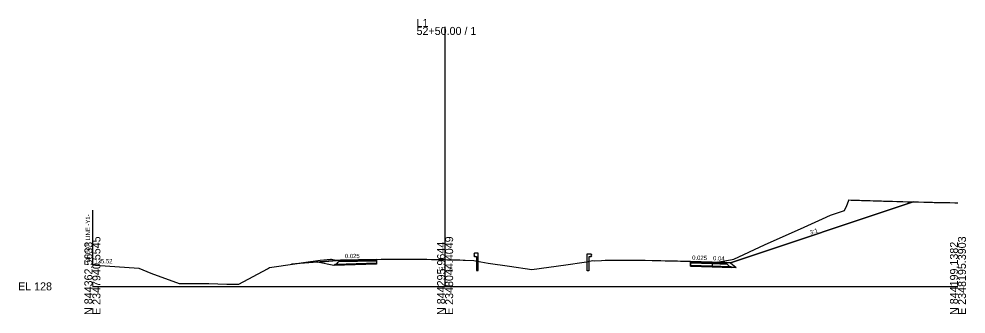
# Model space of a CAD drawing. Extents: x -26 to 2348258, y -10 to 844496.
# Drawn here: x 1302.1 to 1633.4, y 3490.3 to 3593.6 of the extents above; entities that cross this region are included whole.
import ezdxf

# ---------------------------------------------------------------- set-up
doc = ezdxf.new("R2010")
doc.units = 0
for name, color, linetype in [('Exist Cross Section Cell', 7, 'Continuous'), ('Exist XS Center Line Elevation Label', 7, 'Continuous'), ('Exist XS Ground Line', 7, 'Continuous'), ('Prop CMT Guardrail Graphics', 7, 'Continuous'), ('Prop CMT Pvmt Course 1', 7, 'Continuous'), ('Prop CMT Pvmt Course 2', 7, 'Continuous'), ('Prop CMT Pvmt Course 3', 7, 'Continuous'), ('Prop CMT Pvmt Course 4', 7, 'Continuous'), ('Prop CMT Pvmt Surface', 7, 'Continuous'), ('Prop CMT Shld Paved Course 1', 7, 'Continuous'), ('Prop CMT Shld Paved Course 2', 7, 'Continuous'), ('Prop CMT Shld Paved Course 3', 7, 'Continuous'), ('Prop CMT Shld Paved Course 4', 7, 'Continuous'), ('Prop CMT Slope Grass', 7, 'Continuous'), ('Prop CMT Subgrade Earthwork', 7, 'Continuous'), ('Prop XS Earthwork Shape', 7, 'Continuous'), ('Prop XS SE Text', 7, 'Continuous'), ('Prop XS Shear Point Element', 7, 'Continuous'), ('Prop XS Shear Point Label', 7, 'Continuous')]:
    doc.layers.add(name, color=color, linetype=linetype)

msp = doc.modelspace()

# ---------------------------------------------------------------- linework, layer by layer
at = {"layer": 'Exist Cross Section Cell'}
for p, q in [((1451.19, 3500), (1451.19, 3590.79)), ((1327.82, 3500), (1451.19, 3500)), ((1451.19, 3500), (1630.56, 3500))]:
    msp.add_line(p, q, dxfattribs=at)
at = {"layer": 'Exist XS Ground Line'}
msp.add_lwpolyline([(1327.82, 3507.52), (1328.92, 3507.46), (1344.03, 3506.34), (1348.23, 3504.6), (1358.15, 3501.04), (1360.04, 3501.04), (1366.88, 3500.96), (1368.49, 3500.95), (1374.87, 3500.78), (1379.06, 3500.82), (1389.07, 3506.15), (1389.71, 3506.66), (1407.48, 3509.18), (1408.81, 3509.32), (1411.09, 3509.55), (1411.48, 3509.48), (1413.02, 3509.2), (1413.81, 3509.22), (1414.83, 3509.23), (1415.14, 3509.24), (1415.86, 3509.25), (1416.71, 3509.27), (1417.75, 3509.29), (1419.71, 3509.33), (1420.54, 3509.34), (1422.71, 3509.37), (1423.18, 3509.38), (1423.91, 3509.39), (1425.66, 3509.42), (1427.32, 3509.44), (1428.85, 3509.47), (1431.58, 3509.5), (1433.2, 3509.52), (1434.53, 3509.53), (1436.97, 3509.55), (1437.78, 3509.56), (1439.55, 3509.57), (1440.47, 3509.57), (1442.42, 3509.53), (1443.04, 3509.52), (1443.43, 3509.52), (1444.85, 3509.5), (1446.37, 3509.46), (1447.05, 3509.45), (1449.37, 3509.4), (1450.62, 3509.37), (1451.14, 3509.35), (1452, 3509.33), (1452.34, 3509.32), (1453.51, 3509.3), (1455.3, 3509.28), (1456.33, 3509.25), (1457.49, 3509.22), (1458.24, 3509.2), (1461.28, 3509.06), (1463.72, 3508.6), (1466.22, 3508.16), (1473.71, 3507.09), (1481.51, 3505.93), (1493.42, 3507.56), (1499.79, 3508.43), (1500.76, 3508.61), (1502.78, 3509.01), (1503.39, 3508.97), (1505.84, 3509.08), (1507.22, 3509.12), (1508.12, 3509.14), (1508.74, 3509.15), (1510.02, 3509.18), (1511.82, 3509.21), (1512.76, 3509.21), (1513.38, 3509.21), (1514.78, 3509.21), (1515.45, 3509.21), (1516.52, 3509.2), (1517.74, 3509.19), (1519.05, 3509.17), (1521.2, 3509.12), (1523.65, 3509.07), (1525.1, 3509.03), (1526.17, 3509.01), (1526.62, 3509), (1528.1, 3508.98), (1529.55, 3508.95), (1530.36, 3508.94), (1532.52, 3508.89), (1533.5, 3508.86), (1535.1, 3508.82), (1535.64, 3508.81), (1536.93, 3508.79), (1538.49, 3508.68), (1539, 3508.66), (1539.74, 3508.62), (1541.43, 3508.53), (1542.6, 3508.46), (1544.53, 3508.35), (1545.47, 3508.35), (1551.01, 3509.34), (1552.15, 3509.55), (1562.86, 3514.54), (1576.73, 3520.7), (1583.19, 3523.61), (1586.01, 3524.88), (1590.87, 3526.5), (1591.65, 3528.28), (1592.33, 3529.81), (1592.45, 3530.26), (1593.25, 3530.11), (1593.7, 3530.2), (1594.56, 3530.17), (1595.32, 3530.13), (1596.16, 3530.11), (1596.88, 3530.09), (1597.92, 3530.06), (1599.81, 3530), (1600.88, 3529.97), (1602.28, 3529.92), (1603.81, 3529.88), (1604.48, 3529.87), (1605.9, 3529.83), (1606.84, 3529.8), (1607.72, 3529.78), (1609.13, 3529.74), (1609.77, 3529.72), (1611.32, 3529.68), (1612.74, 3529.63), (1613.75, 3529.61), (1614.94, 3529.58), (1615.72, 3529.55), (1616.76, 3529.53), (1618.65, 3529.48), (1620.4, 3529.44), (1621.67, 3529.41), (1622.19, 3529.4), (1623.02, 3529.39), (1624.67, 3529.35), (1627.71, 3529.3), (1629.43, 3529.26), (1630.56, 3529.24)], dxfattribs=at)
at = {"layer": 'Prop CMT Guardrail Graphics'}
for p, q in [((1461.46, 3511.57), (1461.19, 3511.28)), ((1462.79, 3511.57), (1461.46, 3511.57)), ((1462.79, 3505.57), (1462.79, 3511.57)), ((1461.19, 3511.28), (1461.46, 3510.99)), ((1461.46, 3510.99), (1461.19, 3510.69)), ((1461.19, 3510.69), (1461.46, 3510.4)), ((1461.46, 3510.4), (1462.13, 3510.4)), ((1462.13, 3510.4), (1462.13, 3505.57)), ((1500.85, 3505.44), (1500.85, 3511.44)), ((1500.85, 3511.44), (1502.18, 3511.44)), ((1502.18, 3510.28), (1501.51, 3510.28)), ((1501.51, 3510.28), (1501.51, 3505.44)), ((1502.18, 3511.44), (1502.45, 3511.15)), ((1502.45, 3511.15), (1502.18, 3510.86)), ((1502.18, 3510.86), (1502.45, 3510.57)), ((1502.45, 3510.57), (1502.18, 3510.28)), ((1462.13, 3505.57), (1462.79, 3505.57)), ((1501.51, 3505.44), (1500.85, 3505.44))]:
    msp.add_line(p, q, dxfattribs=at)
at = {"layer": 'Prop CMT Pvmt Course 1'}
for p in [(1544.59, 3508.47), (1544.59, 3508.34)]:
    msp.add_line(p, (1544.59, 3508.59), dxfattribs=at)
at = {"layer": 'Prop CMT Pvmt Course 2'}
for p, q in [((1427.19, 3509.19), (1414.29, 3508.87)), ((1537.01, 3508.53), (1544.59, 3508.34)), ((1544.59, 3508.34), (1549.45, 3508.15)), ((1544.59, 3508.01), (1544.59, 3508.34))]:
    msp.add_line(p, q, dxfattribs=at)
at = {"layer": 'Prop CMT Pvmt Course 3'}
for p, q in [((1427.19, 3508.86), (1413.95, 3508.53)), ((1427.19, 3508.85), (1427.19, 3508.06)), ((1537.01, 3508.2), (1544.59, 3508.01)), ((1537.01, 3508.19), (1537.01, 3507.4)), ((1544.59, 3508.01), (1549.8, 3507.8)), ((1544.59, 3508.01), (1544.59, 3507.21))]:
    msp.add_line(p, q, dxfattribs=at)
at = {"layer": 'Prop CMT Pvmt Course 4'}
for p, q in [((1427.19, 3507.73), (1412.31, 3507.36)), ((1427.19, 3508.07), (1413, 3507.71)), ((1427.19, 3507.73), (1427.19, 3508.06)), ((1537.01, 3507.41), (1544.59, 3507.22)), ((1537.01, 3507.07), (1537.01, 3507.4)), ((1537.01, 3507.07), (1544.59, 3506.88)), ((1544.59, 3507.22), (1550.61, 3506.99)), ((1544.59, 3506.88), (1544.59, 3507.21)), ((1544.59, 3506.88), (1551.45, 3506.63))]:
    msp.add_line(p, q, dxfattribs=at)
at = {"layer": 'Prop CMT Pvmt Surface'}
for p, q in [((1427.19, 3509.44), (1414.55, 3509.12)), ((1537.01, 3508.78), (1544.59, 3508.59)), ((1544.59, 3508.59), (1549.19, 3508.41))]:
    msp.add_line(p, q, dxfattribs=at)
at = {"layer": 'Prop CMT Shld Paved Course 1'}
for p, q in [((1414.55, 3509.12), (1414.29, 3508.87)), ((1549.19, 3508.41), (1549.45, 3508.15))]:
    msp.add_line(p, q, dxfattribs=at)
at = {"layer": 'Prop CMT Shld Paved Course 2'}
for p, q in [((1414.29, 3508.87), (1413.95, 3508.53)), ((1549.45, 3508.15), (1549.79, 3507.81))]:
    msp.add_line(p, q, dxfattribs=at)
at = {"layer": 'Prop CMT Shld Paved Course 3'}
for p, q in [((1413.14, 3507.72), (1413.95, 3508.53)), ((1550.6, 3507), (1549.79, 3507.81))]:
    msp.add_line(p, q, dxfattribs=at)
at = {"layer": 'Prop CMT Shld Paved Course 4'}
for p, q in [((1412.64, 3507.7), (1412.31, 3507.36)), ((1413.14, 3507.72), (1412.64, 3507.7)), ((1550.6, 3507), (1551.1, 3506.98)), ((1551.1, 3506.98), (1551.43, 3506.65))]:
    msp.add_line(p, q, dxfattribs=at)
at = {"layer": 'Prop CMT Slope Grass'}
for p, q in [((1551.02, 3508.26), (1614.95, 3529.57)), ((1414.55, 3509.12), (1397.42, 3507.75)), ((1549.19, 3508.41), (1551.02, 3508.26))]:
    msp.add_line(p, q, dxfattribs=at)
at = {"layer": 'Prop CMT Subgrade Earthwork'}
for p, q in [((1427.19, 3509.44), (1427.19, 3507.73)), ((1427.19, 3509.44), (1427.19, 3507.73)), ((1537.01, 3508.78), (1537.01, 3507.07)), ((1537.01, 3508.78), (1537.01, 3507.07)), ((1551.02, 3508.26), (1552.94, 3506.57)), ((1544.59, 3506.88), (1552.94, 3506.57))]:
    msp.add_line(p, q, dxfattribs=at)
for points in [[(1427.19, 3507.73), (1412.31, 3507.36), (1406.61, 3508.49)], [(1537.01, 3507.07), (1544.59, 3506.88)]]:
    msp.add_lwpolyline(points, dxfattribs=at)
at = {"layer": 'Prop XS Earthwork Shape'}
for points in [[(1546.42, 3508.52), (1551.01, 3509.34), (1552.15, 3509.55), (1562.86, 3514.54), (1576.73, 3520.7), (1583.19, 3523.61), (1586.01, 3524.88), (1590.87, 3526.5), (1591.65, 3528.28), (1592.33, 3529.81), (1592.45, 3530.26), (1593.25, 3530.11), (1593.7, 3530.2), (1594.56, 3530.17), (1595.32, 3530.13), (1596.16, 3530.11), (1596.88, 3530.09), (1597.92, 3530.06), (1599.81, 3530), (1600.88, 3529.97), (1602.28, 3529.92), (1603.81, 3529.88), (1604.48, 3529.87), (1605.9, 3529.83), (1606.84, 3529.8), (1607.72, 3529.78), (1609.13, 3529.74), (1609.77, 3529.72), (1611.32, 3529.68), (1612.74, 3529.63), (1613.75, 3529.61), (1614.95, 3529.57), (1551.02, 3508.26), (1549.19, 3508.41)], [(1406.61, 3508.49), (1397.42, 3507.75), (1407.48, 3509.18), (1408.81, 3509.32), (1411.09, 3509.55), (1411.48, 3509.48), (1413.02, 3509.2), (1413.81, 3509.22), (1414.83, 3509.23), (1415.14, 3509.24), (1415.86, 3509.25), (1416.71, 3509.27), (1417.75, 3509.29), (1419.71, 3509.33), (1420.54, 3509.34), (1422.71, 3509.37), (1423.18, 3509.38), (1423.91, 3509.39), (1425.66, 3509.42), (1427.19, 3509.44), (1414.55, 3509.12)], [(1427.19, 3509.44), (1427.19, 3507.73), (1412.31, 3507.36), (1406.61, 3508.49), (1414.55, 3509.12)], [(1546.42, 3508.52), (1549.19, 3508.41), (1551.02, 3508.26), (1552.94, 3506.57), (1544.59, 3506.88), (1537.01, 3507.07), (1537.01, 3508.78), (1538.49, 3508.68), (1539, 3508.66), (1539.74, 3508.62), (1541.43, 3508.53), (1542.6, 3508.46), (1544.53, 3508.35), (1545.47, 3508.35)]]:
    msp.add_lwpolyline(points, close=True, dxfattribs=at)
at = {"layer": 'Prop XS Shear Point Element'}
msp.add_line((1327.82, 3526.68), (1327.82, 3507.52), dxfattribs=at)

# ---------------------------------------------------------------- texts
at = {"layer": 'Exist Cross Section Cell'}
for s, p in [('L1', (1441.19, 3590.79)), ('52+50.00 / 1', (1441.19, 3587.99)), ('EL 128', (1301.82, 3498.6))]:
    msp.add_text(s, height=2.8, dxfattribs=at).set_placement(p)
for s, p in [('N 844362.5633', (1327.82, 3490)), ('E 2347940.5545', (1330.62, 3490)), ('N 844295.9644', (1451.19, 3490)), ('E 2348044.4049', (1453.99, 3490)), ('N 844199.1382', (1630.56, 3490)), ('E 2348195.3903', (1633.36, 3490))]:
    msp.add_text(s, height=2.8, rotation=90, dxfattribs=at).set_placement(p)
at = {"layer": 'Exist XS Center Line Elevation Label'}
msp.add_text('137.35', height=1.2, dxfattribs=at).set_placement((1448.74, 3505.56))
at = {"layer": 'Prop XS SE Text'}
for s, rotation, p in [('3:1', 18.4349, (1579.04, 3518.07)), ('0.025', 358.5679, (1537.58, 3509.32)), ('0.04', 358.0849, (1544.89, 3509.13))]:
    msp.add_text(s, height=1.5, rotation=rotation, dxfattribs=at).set_placement(p)
for s, p in [('135.52', (1328.51, 3508.05)), ('0.025', (1416.12, 3509.88))]:
    msp.add_text(s, height=1.5, dxfattribs=at).set_placement(p)
at = {"layer": 'Prop XS Shear Point Label'}
msp.add_text('SHEAR LINE -Y1-', height=1.5, rotation=90, dxfattribs=at).set_placement((1326.99, 3508.38))

doc.saveas('drawing.dxf')
